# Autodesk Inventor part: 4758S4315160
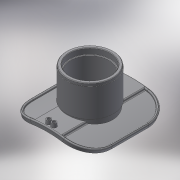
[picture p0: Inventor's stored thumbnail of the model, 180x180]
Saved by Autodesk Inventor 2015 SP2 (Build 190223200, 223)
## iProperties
Created: 2017-08
Part Number: 4758S4315160
Material: Generic
Description: PLASSON WASTEWATER SADDLE 280-315X160 SPIGOT INLET
Document SubType Name: Modeling
Designer: Кирилл
Density: 1 g/cm^3
Appearance: Default
Author: Кирилл
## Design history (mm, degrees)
derived "4758S4.ipt"
feature "Solid1::4758S4.ipt"
feature "Solid2::4758S4.ipt"
feature "Solid3::4758S4.ipt"
tag "TaggingFeature1"
body "Solid1"
other parameters: "d0" = 315, "d1" = 245, "d2" = 343.35, "d4" = 0, "d5" = 73.5, "d6" = 9.6, "d7" = 30 deg, "d8" = 15 deg, "d10" = 0, "d11" = 204.75, "d38" = 1.575, "d40" = 183.5, "d41" = 15, "d42" = 130.5, "d43" = 17.6, "d44" = 8.8, "d46" = 5 deg, "d47" = 4, "d49" = 4, "d51" = 14, "d52" = 0, "d53" = 3, "d54" = 0, "d75" = 0, "d77" = 0, "d78" = 1.6, "d82" = 125, "d84" = 156.8, "d85" = 128, "d86" = 136, "d87" = 18.75, "d88" = 152, "d89" = 18.75, "d90" = 9.375, "d91" = 1.6, "d_" = 315, "B_" = 245, "H_" = 125
